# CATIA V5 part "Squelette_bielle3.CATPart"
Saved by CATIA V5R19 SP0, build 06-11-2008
Part number: Squelette_bielle3
Bounding box of the stored display mesh (mm): x -500 to 500, y 1443.75 to 2865.426, z 134.485 to 329.578
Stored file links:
  C:\Users\Guillaume et Fanny\Documents\IFMA\2A\IAO\Squelette_bielle3.CATPart
  C:\Users\Guillaume et Fanny\Documents\IFMA\2A\IAO\Train d'aterrissage.CATProduct
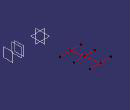
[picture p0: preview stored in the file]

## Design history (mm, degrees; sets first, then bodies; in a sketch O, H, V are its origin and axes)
Set1
  Point1 to Point3: linked copy from another document
Body1 (main body)
  Line1: type PtDir, Direction (1, 0, 0), Start -500, End 500, RefPoint Point1
  Line2: type PtDir, Direction (1, 0, 0), Start -500, End 500, RefPoint Point2
  Line3: type PtDir, Direction (1, 0, 0), Start -500, End 500, RefPoint Point3
  Line4: type PtPt, SecondPoint Point2, FirstPoint Point1
  Line5: type PtPt, SecondPoint Point2, FirstPoint Point3
  Line6: type PtPt, SecondPoint Point3, FirstPoint Point1
  Plane1 "Plan.1120": type Offset, Offset 1120, RefPlane yz-plane
  Plane2 "Plan.1010": type Offset, Offset 1010, RefPlane yz-plane
  Plane3: type Offset, Offset 1520, RefPlane yz-plane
